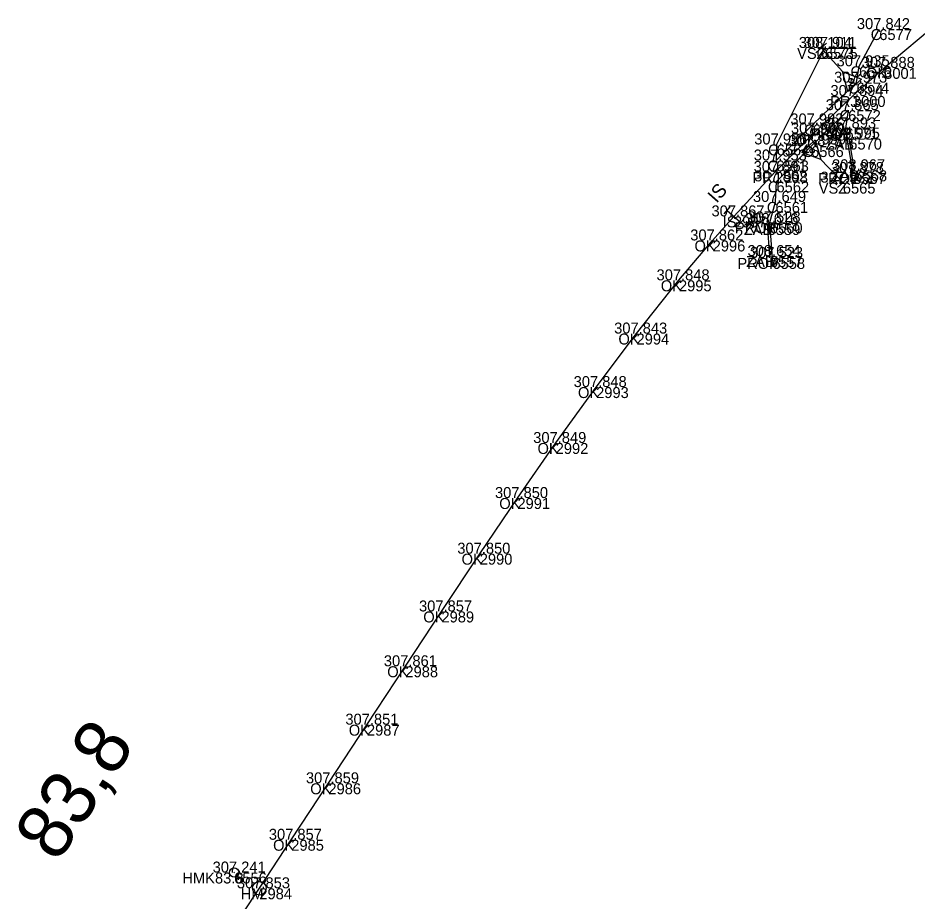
# Model space of a CAD drawing. Extents: x -621782 to -610392, y -1141853 to -1122321.
# Drawn here: x -613464.6 to -613366.3, y -1133061.6 to -1132964.9 of the extents above; entities that cross this region are included whole.
import ezdxf

# ---------------------------------------------------------------- set-up
doc = ezdxf.new("R2010")
doc.units = 0
for name, color, linetype in [('Vrstva 1', 7, 'Continuous'), ('Vrstva 17', 7, 'Continuous'), ('Vrstva 19', 7, 'Continuous'), ('Vrstva 3', 7, 'Continuous'), ('Vrstva 4', 7, 'Continuous'), ('Vrstva 51', 7, 'Continuous'), ('Vrstva 60', 7, 'Continuous'), ('Vrstva 61', 7, 'Continuous'), ('Vrstva 62', 7, 'Continuous'), ('Vrstva 7', 7, 'Continuous')]:
    doc.layers.add(name, color=color, linetype=linetype)

msp = doc.modelspace()

# ---------------------------------------------------------------- linework, layer by layer
at = {"layer": 'Vrstva 1'}
msp.add_lwpolyline([(-613440.021, -1133062.96), (-613438.185, -1133060.17), (-613434.696, -1133054.862), (-613430.635, -1133048.683), (-613426.419, -1133042.269), (-613422.214, -1133035.879), (-613418.272, -1133029.882), (-613414.084, -1133023.562), (-613409.965, -1133017.472), (-613405.782, -1133011.449), (-613401.359, -1133005.332), (-613396.936, -1132999.475), (-613392.299, -1132993.651), (-613388.616, -1132989.29), (-613386.29, -1132986.657), (-613381.773, -1132981.799), (-613377.602, -1132977.588), (-613373.284, -1132973.484), (-613369.86, -1132970.406), (-613363.779, -1132965.29)], dxfattribs=at)
at = {"layer": 'Vrstva 17'}
for p, q in [((-613373.109, -1132981.609), (-613373.676, -1132978.141)), ((-613382.352, -1132991.001), (-613382.608, -1132987.493))]:
    msp.add_line(p, q, dxfattribs=at)
at = {"layer": 'Vrstva 19'}
for p, q in [((-613373.236, -1132981.912), (-613374.092, -1132977.023)), ((-613382.079, -1132991.203), (-613382.35, -1132987.309))]:
    msp.add_line(p, q, dxfattribs=at)
at = {"layer": 'Vrstva 3'}
for p, q in [((-613387.37, -1132986.37), (-613386.708, -1132985.62)), ((-613387.039, -1132985.995), (-613385.541, -1132987.319)), ((-613385.872, -1132987.694), (-613385.21, -1132986.944))]:
    msp.add_line(p, q, dxfattribs=at)
at = {"layer": 'Vrstva 4'}
for p, q in [((-613376.16, -1132967.708), (-613377.322, -1132968.744)), ((-613373.469, -1132971.565), (-613373.5, -1132972.053)), ((-613377.743, -1132979.719), (-613377.726, -1132979.23)), ((-613374.946, -1132983.5), (-613373.814, -1132982.432))]:
    msp.add_line(p, q, dxfattribs=at)
for points in [[(-613376.741, -1132968.226), (-613374.419, -1132970.814), (-613372.344, -1132971.648), (-613373.828, -1132972.987), (-613374.419, -1132970.814)], [(-613381.773, -1132981.799), (-613377.602, -1132977.588), (-613373.284, -1132973.484)], [(-613374.38, -1132982.966), (-613376.773, -1132980.444), (-613378.87, -1132979.667), (-613377.424, -1132978.288), (-613376.773, -1132980.444)]]:
    msp.add_lwpolyline(points, dxfattribs=at)
for centre in [(-613373.486, -1132971.808), (-613377.734, -1132979.476)]:
    msp.add_circle(centre, 0.248, dxfattribs=at)
at = {"layer": 'Vrstva 51'}
for points in [[(-613376.332, -1132968.223), (-613381.617, -1132978.784), (-613381.668, -1132980.54), (-613377.673, -1132976.594), (-613372.882, -1132972.021), (-613372.605, -1132970.232), (-613370.396, -1132966.165)], [(-613382.35, -1132987.309), (-613381.752, -1132985.076), (-613381.638, -1132982.826), (-613377.851, -1132978.964), (-613373.796, -1132975.034), (-613374.092, -1132977.023)]]:
    msp.add_lwpolyline(points, dxfattribs=at)
at = {"layer": 'Vrstva 60'}
for p, q in [((-613370.396, -1132966.165), (-613370.396, -1132966.165)), ((-613376.741, -1132968.226), (-613376.741, -1132968.226)), ((-613376.332, -1132968.223), (-613376.332, -1132968.223)), ((-613372.605, -1132970.232), (-613372.605, -1132970.232)), ((-613369.86, -1132970.406), (-613369.86, -1132970.406)), ((-613372.882, -1132972.021), (-613372.882, -1132972.021)), ((-613373.284, -1132973.484), (-613373.284, -1132973.484)), ((-613373.796, -1132975.034), (-613373.796, -1132975.034)), ((-613377.673, -1132976.594), (-613377.673, -1132976.594)), ((-613374.092, -1132977.023), (-613374.092, -1132977.023)), ((-613377.602, -1132977.588), (-613377.602, -1132977.588)), ((-613381.617, -1132978.784), (-613381.617, -1132978.784)), ((-613377.851, -1132978.964), (-613377.851, -1132978.964)), ((-613373.676, -1132978.141), (-613373.676, -1132978.141)), ((-613381.668, -1132980.54), (-613381.668, -1132980.54)), ((-613381.773, -1132981.799), (-613381.773, -1132981.799)), ((-613373.236, -1132981.912), (-613373.236, -1132981.912)), ((-613373.109, -1132981.609), (-613373.109, -1132981.609)), ((-613381.638, -1132982.826), (-613381.638, -1132982.826)), ((-613374.38, -1132982.966), (-613374.38, -1132982.966)), ((-613381.752, -1132985.076), (-613381.752, -1132985.076)), ((-613386.29, -1132986.657), (-613386.29, -1132986.657)), ((-613382.608, -1132987.493), (-613382.608, -1132987.493)), ((-613382.35, -1132987.309), (-613382.35, -1132987.309)), ((-613388.616, -1132989.29), (-613388.616, -1132989.29)), ((-613382.352, -1132991.001), (-613382.352, -1132991.001)), ((-613382.079, -1132991.203), (-613382.079, -1132991.203)), ((-613392.299, -1132993.651), (-613392.299, -1132993.651)), ((-613396.936, -1132999.475), (-613396.936, -1132999.475)), ((-613401.359, -1133005.332), (-613401.359, -1133005.332)), ((-613405.782, -1133011.449), (-613405.782, -1133011.449)), ((-613409.965, -1133017.472), (-613409.965, -1133017.472)), ((-613414.084, -1133023.562), (-613414.084, -1133023.562)), ((-613418.272, -1133029.882), (-613418.272, -1133029.882)), ((-613422.214, -1133035.879), (-613422.214, -1133035.879)), ((-613426.419, -1133042.269), (-613426.419, -1133042.269)), ((-613430.635, -1133048.683), (-613430.635, -1133048.683)), ((-613434.696, -1133054.862), (-613434.696, -1133054.862)), ((-613440.935, -1133058.446), (-613440.935, -1133058.446)), ((-613438.185, -1133060.17), (-613438.185, -1133060.17))]:
    msp.add_line(p, q, dxfattribs=at)
at = {"layer": 'Vrstva 7'}
msp.add_line((-613440.962, -1133058.488), (-613440.908, -1133058.404), dxfattribs=at)
for centre, radius in [((-613440.935, -1133058.446), 0.5), ((-613438.185, -1133060.17), 0.75)]:
    msp.add_circle(centre, radius, dxfattribs=at)

# ---------------------------------------------------------------- texts
at = {"layer": 'Vrstva 3'}
msp.add_text('IS', height=1.5, rotation=48.54253, dxfattribs=at).set_placement((-613388.179, -1132985.284))
at = {"layer": 'Vrstva 60'}
for s, p in [('6577', (-613370.396, -1132967.365)), ('6573', (-613376.741, -1132969.426)), ('6575', (-613376.332, -1132969.423)), ('6576', (-613372.605, -1132971.432)), ('3001', (-613369.86, -1132971.606)), ('6574', (-613372.882, -1132973.221)), ('3000', (-613373.284, -1132974.684)), ('6572', (-613373.796, -1132976.234)), ('6569', (-613377.673, -1132977.794)), ('6571', (-613374.092, -1132978.223)), ('2999', (-613377.602, -1132978.788)), ('6564', (-613381.617, -1132979.984)), ('6566', (-613377.851, -1132980.164)), ('6570', (-613373.676, -1132979.341)), ('6563', (-613381.668, -1132981.74)), ('2998', (-613381.773, -1132982.999)), ('6567', (-613373.236, -1132983.112)), ('6568', (-613373.109, -1132982.809)), ('6562', (-613381.638, -1132984.026)), ('6565', (-613374.38, -1132984.166)), ('6561', (-613381.752, -1132986.276)), ('2997', (-613386.29, -1132987.857)), ('6559', (-613382.608, -1132988.693)), ('6560', (-613382.35, -1132988.509)), ('2996', (-613388.616, -1132990.49)), ('6557', (-613382.352, -1132992.201)), ('6558', (-613382.079, -1132992.403)), ('2995', (-613392.299, -1132994.851)), ('2994', (-613396.936, -1133000.675)), ('2993', (-613401.359, -1133006.532)), ('2992', (-613405.782, -1133012.649)), ('2991', (-613409.965, -1133018.672)), ('2990', (-613414.084, -1133024.762)), ('2989', (-613418.272, -1133031.082)), ('2988', (-613422.214, -1133037.079)), ('2987', (-613426.419, -1133043.469)), ('2986', (-613430.635, -1133049.883)), ('2985', (-613434.696, -1133056.062)), ('6556', (-613440.935, -1133059.646)), ('2984', (-613438.185, -1133061.37))]:
    msp.add_text(s, height=1.2, dxfattribs=at).set_placement(p)
at = {"layer": 'Vrstva 61'}
for s, p in [('307.842', (-613372.844, -1132966.165)), ('308.104', (-613379.192, -1132968.226)), ('307.911', (-613378.689, -1132968.223)), ('307.935', (-613375.061, -1132970.232)), ('307.888', (-613372.314, -1132970.406)), ('307.973', (-613375.334, -1132972.021)), ('307.894', (-613375.735, -1132973.484)), ('307.865', (-613376.252, -1132975.034)), ('307.982', (-613380.121, -1132976.594)), ('307.893', (-613376.544, -1132977.023)), ('307.900', (-613380.053, -1132977.588)), ('308.995', (-613376.132, -1132978.141)), ('307.956', (-613384.069, -1132978.784)), ('307.875', (-613380.307, -1132978.964)), ('307.953', (-613384.12, -1132980.54)), ('307.891', (-613384.13, -1132981.799)), ('307.878', (-613375.69, -1132981.912)), ('308.967', (-613375.561, -1132981.609)), ('307.862', (-613384.086, -1132982.826)), ('307.932', (-613376.828, -1132982.966)), ('307.649', (-613384.206, -1132985.076)), ('307.867', (-613388.742, -1132986.657)), ('308.616', (-613385.06, -1132987.493)), ('307.528', (-613384.804, -1132987.309)), ('307.862', (-613391.064, -1132989.29)), ('308.654', (-613384.803, -1132991.001)), ('307.523', (-613384.531, -1132991.203)), ('307.848', (-613394.753, -1132993.651)), ('307.843', (-613399.388, -1132999.475)), ('307.848', (-613403.813, -1133005.332)), ('307.849', (-613408.236, -1133011.449)), ('307.850', (-613412.416, -1133017.472)), ('307.850', (-613416.535, -1133023.562)), ('307.857', (-613420.724, -1133029.882)), ('307.861', (-613424.571, -1133035.879)), ('307.851', (-613428.776, -1133042.269)), ('307.859', (-613433.089, -1133048.683)), ('307.857', (-613437.148, -1133054.862)), ('307.241', (-613443.292, -1133058.446)), ('307.853', (-613440.637, -1133060.17))]:
    msp.add_text(s, height=1.2, dxfattribs=at).set_placement(p)
at = {"layer": 'Vrstva 62'}
for s, p in [('C', (-613371.332, -1132967.365)), ('VSZ', (-613379.381, -1132969.426)), ('C', (-613377.268, -1132969.423)), ('C', (-613373.541, -1132971.432)), ('OK', (-613371.845, -1132971.606)), ('C', (-613373.818, -1132973.221)), ('PRJ', (-613375.77, -1132974.684)), ('C', (-613374.732, -1132976.234)), ('C', (-613378.609, -1132977.794)), ('PROP', (-613377.926, -1132978.223)), ('OK', (-613379.587, -1132978.788)), ('C', (-613382.553, -1132979.984)), ('C', (-613378.787, -1132980.164)), ('ZAB', (-613376.277, -1132979.341)), ('C', (-613382.604, -1132981.74)), ('PRJ', (-613384.259, -1132982.999)), ('PROP', (-613377.07, -1132983.112)), ('ZAB', (-613375.71, -1132982.809)), ('C', (-613382.574, -1132984.026)), ('VSZ', (-613377.02, -1132984.166)), ('C', (-613382.688, -1132986.276)), ('IS', (-613387.519, -1132987.857)), ('PROP', (-613386.184, -1132988.509)), ('ZAB', (-613385.209, -1132988.693)), ('OK', (-613390.601, -1132990.49)), ('PROP', (-613385.913, -1132992.403)), ('ZAB', (-613384.953, -1132992.201)), ('OK', (-613394.284, -1132994.851)), ('OK', (-613398.921, -1133000.675)), ('OK', (-613403.344, -1133006.532)), ('OK', (-613407.767, -1133012.649)), ('OK', (-613411.95, -1133018.672)), ('OK', (-613416.069, -1133024.762)), ('OK', (-613420.257, -1133031.082)), ('OK', (-613424.199, -1133037.079)), ('OK', (-613428.404, -1133043.469)), ('OK', (-613432.62, -1133049.883)), ('OK', (-613436.681, -1133056.062)), ('HMK83.8', (-613446.603, -1133059.646)), ('HM', (-613440.218, -1133061.37))]:
    msp.add_text(s, height=1.2, dxfattribs=at).set_placement(p)
at = {"layer": 'Vrstva 7'}
msp.add_text('83,8', height=6, rotation=56.68918, dxfattribs=at).set_placement((-613460.27, -1133057.489))

doc.saveas('drawing.dxf')
